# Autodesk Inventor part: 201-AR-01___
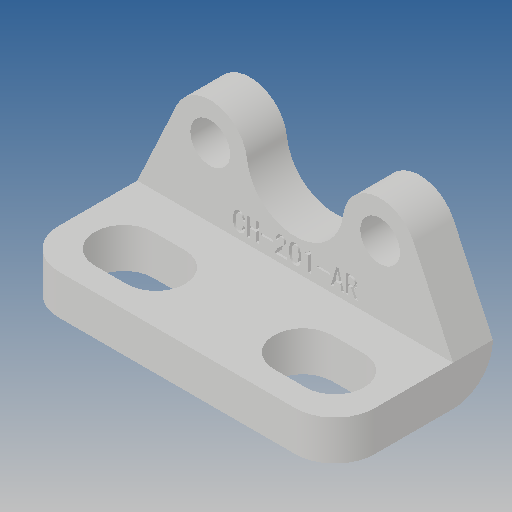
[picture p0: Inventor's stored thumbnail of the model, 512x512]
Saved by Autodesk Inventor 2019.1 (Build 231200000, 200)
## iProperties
Created: 2010-06
Part Number: 201-AR-01___
Material: Ogólny
Document SubType Name: Modeling
Designer: CADENGINEERING4
Density: 1 g/cm^3
Appearance: Domyślna
Author: CADENGINEERING4
Revision Number: ANY
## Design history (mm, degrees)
feature "NONE"
node "Bryła1"
